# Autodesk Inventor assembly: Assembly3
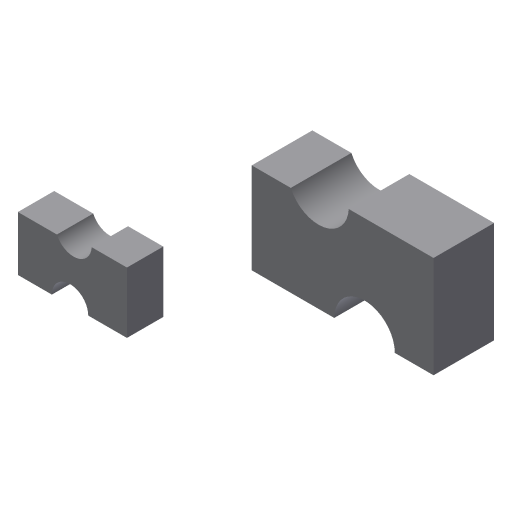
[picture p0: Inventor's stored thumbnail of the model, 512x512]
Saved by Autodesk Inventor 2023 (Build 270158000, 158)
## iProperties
Created: 2017-06
Part Number: Assembly3
Document SubType Name: Assembly
Designer: CADCIM 00
Author: CADCIM 00
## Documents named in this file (4)
- D:\PROJECTS\Project 2022\Autodesk Inventor For Professional 2023\RESOURCES INVENTOR 2023\RESOURCES INVENTOR 2023\Inventor_2023_tut\Inventor_2023_tut\c18_Inv_2023_tut\c18_Inv_tut_2023\c18_tut04_inv\Assembly3.iam
- D:\PROJECTS\Project 2022\Autodesk Inventor For Professional 2023\RESOURCES INVENTOR 2023\RESOURCES INVENTOR 2023\Inventor_2023_tut\Inventor_2023_tut\c18_Inv_2023_tut\c18_Inv_tut_2023\c18_tut04_inv\c18_tut04_inv-01.ipt
- E:\_Deepak\Inventor\Autodesk Inventor_2017_Project\Resources\Inventor_2018_tut\c18_Inv_tut_2018\c18_tut04_inv\c18_tut04_inv.ipt
- D:\PROJECTS\Project 2022\Autodesk Inventor For Professional 2023\RESOURCES INVENTOR 2023\RESOURCES INVENTOR 2023\Inventor_2023_tut\Inventor_2023_tut\c18_Inv_2023_tut\c18_Inv_tut_2023\c18_tut04_inv\c18_tut04_inv-011.ipt
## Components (2 placed, 2 different names)
1. c18_tut04_inv-01:1
2. c18_tut04_inv-011:2
